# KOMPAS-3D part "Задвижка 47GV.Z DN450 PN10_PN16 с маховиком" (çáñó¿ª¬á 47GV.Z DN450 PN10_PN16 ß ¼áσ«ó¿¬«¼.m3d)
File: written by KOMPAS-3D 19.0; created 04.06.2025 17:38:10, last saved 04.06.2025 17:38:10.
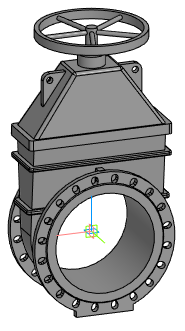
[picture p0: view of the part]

Document properties: Автор: Евгений; Полное имя файла: E:\Dendor Работа Сачек\3D для проекитирвщиков\2.1 Тип 47GV, 47GV.Z Задвижка клиновая фланцевая с обрезиненным клином\stp_Тип 47GV.Z. Задвижка DN40-DN350 с маховиком\Задвижка 47GV.Z DN450 PN10_PN16 с маховиком.m3d

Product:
- Part/product: Задвижка 47GV.Z DN450 PN10_PN16 с маховиком

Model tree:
1. Операция без истории:1  (labels: Задвижка 47GV.Z DN450 PN10_PN16 с маховиком)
